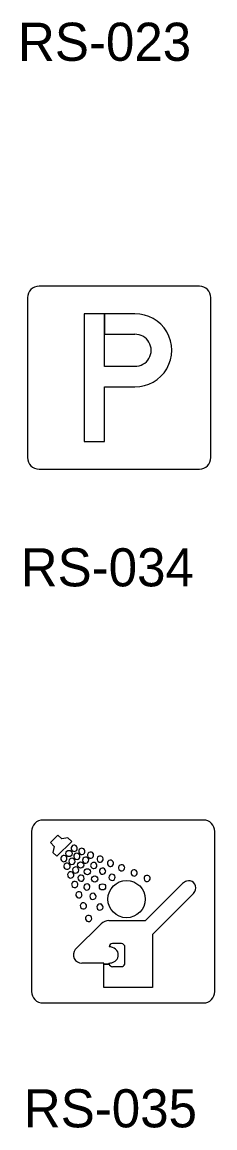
# Model space of a CAD drawing. Extents: x 42133 to 45533, y 41351 to 47951.
# Drawn here: x 42901.3 to 42939.1, y 41989.2 to 42206.7 of the extents above; entities that cross this region are included whole.
import ezdxf

# ---------------------------------------------------------------- set-up
doc = ezdxf.new("R2010")
doc.units = 0
doc.layers.add('P_TRAF_SIGN_SignDetails', color=7, linetype='Continuous')

msp = doc.modelspace()

# ---------------------------------------------------------------- linework, layer by layer
at = {"layer": 'P_TRAF_SIGN_SignDetails'}
for p, q in [((42936.11, 42154.77), (42904.63, 42154.77)), ((42902.38, 42152.52), (42902.38, 42121.03)), ((42938.36, 42121.03), (42938.36, 42152.52)), ((42904.63, 42118.78), (42936.11, 42118.78)), ((42936.89, 42049.76), (42905.42, 42049.76)), ((42903.17, 42047.51), (42903.17, 42016.03)), ((42939.15, 42016.03), (42939.15, 42047.51)), ((42905.42, 42013.78), (42936.89, 42013.78))]:
    msp.add_line(p, q, dxfattribs=at)
for points in [[(42917.5, 42149.32), (42913.48, 42149.32), (42913.48, 42124.21), (42917.5, 42124.21), (42917.5, 42134.98), (42923.43, 42134.98)], [(42923.43, 42149.32), (42917.5, 42149.32), (42917.5, 42145.31), (42923.43, 42145.31)], [(42923.43, 42138.99), (42917.5, 42138.99), (42917.5, 42149.32)], [(42918.34, 42029.97), (42925.55, 42029.97), (42932.82, 42037.26)], [(42918.34, 42029.97), (42925.55, 42029.97), (42932.82, 42037.26)], [(42918.34, 42029.97), (42925.55, 42029.97), (42932.82, 42037.26)], [(42934.86, 42035.23), (42926.89, 42027.23), (42926.89, 42016.79), (42917.34, 42016.79), (42917.34, 42021.62), (42913.02, 42021.62)], [(42934.86, 42035.23), (42926.89, 42027.23), (42926.89, 42016.79), (42917.34, 42016.79), (42917.34, 42021.43), (42918.39, 42021.43)], [(42934.86, 42035.23), (42926.89, 42027.23), (42926.89, 42016.79), (42917.34, 42016.79), (42917.34, 42021.43), (42918.39, 42021.43)], [(42911.74, 42024.27), (42916.83, 42029.37)], [(42911.74, 42024.27), (42916.83, 42029.37)], [(42911.74, 42024.27), (42916.83, 42029.37)], [(42920.77, 42025.45), (42919.08, 42025.45)], [(42920.77, 42025.45), (42919.08, 42025.45)], [(42920.77, 42025.45), (42919.08, 42025.45)], [(42921.49, 42021.62), (42921.49, 42024.74)], [(42921.49, 42021.62), (42921.49, 42024.74)], [(42921.49, 42021.62), (42921.49, 42024.74)], [(42918.39, 42021.43), (42917.34, 42021.43), (42917.34, 42021.62), (42913.02, 42021.62)], [(42918.39, 42021.43), (42917.34, 42021.43), (42917.34, 42021.62), (42913.02, 42021.62)], [(42919.08, 42020.92), (42919.08, 42020.92), (42920.77, 42020.92), (42920.77, 42020.92)], [(42919.08, 42020.92), (42919.08, 42020.92), (42920.77, 42020.92), (42920.77, 42020.92)], [(42919.08, 42020.92), (42919.08, 42020.92), (42920.77, 42020.92), (42920.77, 42020.92)]]:
    msp.add_lwpolyline(points, dxfattribs=at)
msp.add_lwpolyline([(42907.37, 42043.35), (42908.11, 42042.62), (42911.05, 42045.56), (42910.31, 42046.29), (42909.08, 42046.06), (42908.35, 42046.79), (42906.87, 42045.32), (42907.61, 42044.58)], close=True, dxfattribs=at)
msp.add_lwpolyline([(42907.37, 42043.35), (42908.11, 42042.62), (42911.05, 42045.56), (42910.31, 42046.29), (42909.08, 42046.06), (42908.35, 42046.79), (42906.87, 42045.32), (42907.61, 42044.58)], close=True, dxfattribs=at)
msp.add_lwpolyline([(42907.37, 42043.35), (42908.11, 42042.62), (42911.05, 42045.56), (42910.31, 42046.29), (42909.08, 42046.06), (42908.35, 42046.79), (42906.87, 42045.32), (42907.61, 42044.58)], close=True, dxfattribs=at)
for centre, radius in [((42910.51, 42043.18), 0.611), ((42910.51, 42043.18), 0.611), ((42910.51, 42043.18), 0.611), ((42912.8, 42040.91), 0.605), ((42912.8, 42040.91), 0.605), ((42912.8, 42040.91), 0.605), ((42914.12, 42039.58), 0.605), ((42914.12, 42039.58), 0.605), ((42914.12, 42039.58), 0.605), ((42915.56, 42038.15), 0.605), ((42915.56, 42038.15), 0.605), ((42915.56, 42038.15), 0.605), ((42917.09, 42036.62), 0.605), ((42917.09, 42036.62), 0.605), ((42917.09, 42036.62), 0.605), ((42921.81, 42034.2), 3.66), ((42921.81, 42034.2), 3.66), ((42921.81, 42034.2), 3.66)]:
    msp.add_circle(centre, radius, dxfattribs=at)
for centre, radius, start, end in [((42904.63, 42152.51), 2.25, 90, 180), ((42936.11, 42152.51), 2.25, 360, 90), ((42923.52, 42142.15), 7.17, 269.2807, 90.7193), ((42923.5, 42142.15), 3.15, 268.7196, 91.2804), ((42904.63, 42121.04), 2.25, 180, 270), ((42936.11, 42121.04), 2.25, 270, 0), ((42905.42, 42047.51), 2.25, 90, 180), ((42936.9, 42047.51), 2.25, 360, 90), ((42911.53, 42044.2), 0.614, 98.3789, 188.1597), ((42911.53, 42044.2), 0.614, 98.3789, 188.1597), ((42911.53, 42044.2), 0.614, 98.3789, 188.1597), ((42911.53, 42044.21), 0.61, 8.0336, 98.2816), ((42911.53, 42044.21), 0.61, 8.0336, 98.2816), ((42911.53, 42044.21), 0.61, 8.0336, 98.2816), ((42909.5, 42042.17), 0.611, 81.7795, 171.9093), ((42909.5, 42042.17), 0.611, 81.7795, 171.9093), ((42909.5, 42042.17), 0.611, 81.7795, 171.9093), ((42909.5, 42042.17), 0.612, 351.7168, 81.6536), ((42909.5, 42042.17), 0.612, 351.7168, 81.6536), ((42909.5, 42042.17), 0.612, 351.7168, 81.6536), ((42911.53, 42044.2), 0.611, 188.2859, 278.3788), ((42911.53, 42044.2), 0.611, 188.2859, 278.3788), ((42911.53, 42044.2), 0.611, 188.2859, 278.3788), ((42912.06, 42042.61), 0.606, 92.7577, 182.6456), ((42912.06, 42042.61), 0.606, 92.7577, 182.6456), ((42912.06, 42042.61), 0.606, 92.7577, 182.6456), ((42912.06, 42042.61), 0.603, 182.5563, 272.9843), ((42912.06, 42042.61), 0.603, 182.5563, 272.9843), ((42912.06, 42042.61), 0.603, 182.5563, 272.9843), ((42911.53, 42044.2), 0.611, 278.3153, 8.2319), ((42911.53, 42044.2), 0.611, 278.3153, 8.2319), ((42911.53, 42044.2), 0.611, 278.3153, 8.2319), ((42912.06, 42042.61), 0.607, 2.9827, 92.63), ((42912.06, 42042.61), 0.607, 2.9827, 92.63), ((42912.06, 42042.61), 0.607, 2.9827, 92.63), ((42912.06, 42042.62), 0.605, 272.6978, 2.7441), ((42912.06, 42042.62), 0.605, 272.6978, 2.7441), ((42912.06, 42042.62), 0.605, 272.6978, 2.7441), ((42913.03, 42043.59), 0.612, 98.2969, 188.2579), ((42913.03, 42043.59), 0.612, 98.2969, 188.2579), ((42913.03, 42043.59), 0.612, 98.2969, 188.2579), ((42913.03, 42043.59), 0.609, 188.2026, 278.4745), ((42913.03, 42043.59), 0.609, 188.2026, 278.4745), ((42913.03, 42043.59), 0.609, 188.2026, 278.4745), ((42913.03, 42043.59), 0.611, 8.1756, 98.3437), ((42913.03, 42043.59), 0.611, 8.1756, 98.3437), ((42913.03, 42043.59), 0.611, 8.1756, 98.3437), ((42913.04, 42043.59), 0.61, 278.1, 8.2388), ((42913.04, 42043.59), 0.61, 278.1, 8.2388), ((42913.04, 42043.59), 0.61, 278.1, 8.2388), ((42913.77, 42041.88), 0.604, 93.884, 184.3141), ((42913.77, 42041.88), 0.604, 93.884, 184.3141), ((42913.77, 42041.88), 0.604, 93.884, 184.3141), ((42913.78, 42041.88), 0.603, 3.8929, 94.4102), ((42913.78, 42041.88), 0.603, 3.8929, 94.4102), ((42913.78, 42041.88), 0.603, 3.8929, 94.4102), ((42914.75, 42042.85), 0.613, 98.3393, 188.1643), ((42914.75, 42042.85), 0.613, 98.3393, 188.1643), ((42914.75, 42042.85), 0.613, 98.3393, 188.1643), ((42914.75, 42042.86), 0.612, 188.4062, 278.2076), ((42914.75, 42042.86), 0.612, 188.4062, 278.2076), ((42914.75, 42042.86), 0.612, 188.4062, 278.2076), ((42914.75, 42042.86), 0.612, 8.3424, 98.1774), ((42914.75, 42042.86), 0.612, 8.3424, 98.1774), ((42914.75, 42042.86), 0.612, 8.3424, 98.1774), ((42914.75, 42042.86), 0.611, 278.2485, 8.381), ((42914.75, 42042.86), 0.611, 278.2485, 8.381), ((42914.75, 42042.86), 0.611, 278.2485, 8.381), ((42916.62, 42042.07), 0.613, 98.3449, 188.1744), ((42916.62, 42042.07), 0.613, 98.3449, 188.1744), ((42916.62, 42042.07), 0.613, 98.3449, 188.1744), ((42916.62, 42042.07), 0.613, 8.3603, 98.0768), ((42916.62, 42042.07), 0.613, 8.3603, 98.0768), ((42916.62, 42042.07), 0.613, 8.3603, 98.0768), ((42909.5, 42042.17), 0.612, 171.7201, 261.6504), ((42909.5, 42042.17), 0.612, 171.7201, 261.6504), ((42909.5, 42042.17), 0.612, 171.7201, 261.6504), ((42909.5, 42042.17), 0.612, 261.9115, 351.7773), ((42909.5, 42042.17), 0.612, 261.9115, 351.7773), ((42909.5, 42042.17), 0.612, 261.9115, 351.7773), ((42910.12, 42040.67), 0.611, 81.7191, 171.9343), ((42910.12, 42040.67), 0.611, 81.7191, 171.9343), ((42910.12, 42040.67), 0.611, 81.7191, 171.9343), ((42910.12, 42040.67), 0.612, 171.9294, 261.779), ((42910.12, 42040.67), 0.612, 171.9294, 261.779), ((42910.12, 42040.67), 0.612, 171.9294, 261.779), ((42910.12, 42040.67), 0.611, 261.7105, 351.758), ((42910.12, 42040.67), 0.611, 261.7105, 351.758), ((42910.12, 42040.67), 0.611, 261.7105, 351.758), ((42910.12, 42040.67), 0.613, 351.859, 81.6374), ((42910.12, 42040.67), 0.613, 351.859, 81.6374), ((42910.12, 42040.67), 0.613, 351.859, 81.6374), ((42911.09, 42041.64), 0.606, 87.2417, 177.1589), ((42911.09, 42041.64), 0.606, 87.2417, 177.1589), ((42911.09, 42041.64), 0.606, 87.2417, 177.1589), ((42911.09, 42041.64), 0.606, 177.174, 267.1788), ((42911.09, 42041.64), 0.606, 177.174, 267.1788), ((42911.09, 42041.64), 0.606, 177.174, 267.1788), ((42911.09, 42041.64), 0.606, 267.2609, 87.2012), ((42911.09, 42041.64), 0.606, 267.2609, 87.2012), ((42911.09, 42041.64), 0.606, 267.2609, 87.2012), ((42911.82, 42039.93), 0.606, 85.8519, 175.9499), ((42911.82, 42039.93), 0.606, 85.8519, 175.9499), ((42911.82, 42039.93), 0.606, 85.8519, 175.9499), ((42911.82, 42039.93), 0.606, 355.8366, 85.9653), ((42911.82, 42039.93), 0.606, 355.8366, 85.9653), ((42911.82, 42039.93), 0.606, 355.8366, 85.9653), ((42913.77, 42041.88), 0.604, 184.0395, 274.3235), ((42913.77, 42041.88), 0.604, 184.0395, 274.3235), ((42913.77, 42041.88), 0.604, 184.0395, 274.3235), ((42913.78, 42041.88), 0.605, 273.9416, 4.2047), ((42913.78, 42041.88), 0.605, 273.9416, 4.2047), ((42913.78, 42041.88), 0.605, 273.9416, 4.2047), ((42915.37, 42040.83), 0.606, 94.0532, 274.152), ((42915.37, 42040.83), 0.606, 94.0532, 274.152), ((42915.37, 42040.83), 0.606, 94.0532, 274.152), ((42915.37, 42040.83), 0.606, 4.1132, 94.2566), ((42915.37, 42040.83), 0.606, 4.1132, 94.2566), ((42915.37, 42040.83), 0.606, 4.1132, 94.2566), ((42915.37, 42040.83), 0.607, 274.1331, 4.0182), ((42915.37, 42040.83), 0.607, 274.1331, 4.0182), ((42915.37, 42040.83), 0.607, 274.1331, 4.0182), ((42916.62, 42042.08), 0.612, 188.2324, 278.13), ((42916.62, 42042.08), 0.612, 188.2324, 278.13), ((42916.62, 42042.08), 0.612, 188.2324, 278.13), ((42917.1, 42039.7), 0.608, 94.2402, 184.0486), ((42917.1, 42039.7), 0.608, 94.2402, 184.0486), ((42917.1, 42039.7), 0.608, 94.2402, 184.0486), ((42916.62, 42042.08), 0.613, 278.3364, 8.2142), ((42916.62, 42042.08), 0.613, 278.3364, 8.2142), ((42916.62, 42042.08), 0.613, 278.3364, 8.2142), ((42917.1, 42039.7), 0.606, 4.163, 94.155), ((42917.1, 42039.7), 0.606, 4.163, 94.155), ((42917.1, 42039.7), 0.606, 4.163, 94.155), ((42918.65, 42041.25), 0.61, 98.2215, 188.408), ((42918.65, 42041.25), 0.61, 98.2215, 188.408), ((42918.65, 42041.25), 0.61, 98.2215, 188.408), ((42918.65, 42041.24), 0.609, 188.2429, 278.4147), ((42918.65, 42041.24), 0.609, 188.2429, 278.4147), ((42918.65, 42041.24), 0.609, 188.2429, 278.4147), ((42918.65, 42041.25), 0.61, 8.0113, 98.2999), ((42918.65, 42041.25), 0.61, 8.0113, 98.2999), ((42918.65, 42041.25), 0.61, 8.0113, 98.2999), ((42918.65, 42041.24), 0.607, 277.9783, 8.3923), ((42918.65, 42041.24), 0.607, 277.9783, 8.3923), ((42918.65, 42041.24), 0.607, 277.9783, 8.3923), ((42920.84, 42040.37), 0.611, 98.303, 188.3265), ((42920.84, 42040.37), 0.611, 98.303, 188.3265), ((42920.84, 42040.37), 0.611, 98.303, 188.3265), ((42920.84, 42040.36), 0.613, 8.4005, 98.0718), ((42920.84, 42040.36), 0.613, 8.4005, 98.0718), ((42920.84, 42040.36), 0.613, 8.4005, 98.0718), ((42920.84, 42040.37), 0.613, 278.3772, 8.1893), ((42920.84, 42040.37), 0.613, 278.3772, 8.1893), ((42920.84, 42040.37), 0.613, 278.3772, 8.1893), ((42910.85, 42038.96), 0.613, 81.8385, 171.6579), ((42910.85, 42038.96), 0.613, 81.8385, 171.6579), ((42910.85, 42038.96), 0.613, 81.8385, 171.6579), ((42910.85, 42038.96), 0.613, 171.8845, 261.6236), ((42910.85, 42038.96), 0.613, 171.8845, 261.6236), ((42910.85, 42038.96), 0.613, 171.8845, 261.6236), ((42910.85, 42038.96), 0.613, 261.9442, 351.7289), ((42910.85, 42038.96), 0.613, 261.9442, 351.7289), ((42910.85, 42038.96), 0.613, 261.9442, 351.7289), ((42910.85, 42038.96), 0.611, 351.7206, 81.7478), ((42910.85, 42038.96), 0.611, 351.7206, 81.7478), ((42910.85, 42038.96), 0.611, 351.7206, 81.7478), ((42911.82, 42039.93), 0.607, 176.0031, 265.8896), ((42911.82, 42039.93), 0.607, 176.0031, 265.8896), ((42911.82, 42039.93), 0.607, 176.0031, 265.8896), ((42911.82, 42039.93), 0.605, 265.7806, 355.9164), ((42911.82, 42039.93), 0.605, 265.7806, 355.9164), ((42911.82, 42039.93), 0.605, 265.7806, 355.9164), ((42912.88, 42038.33), 0.605, 85.7154, 176.0265), ((42912.88, 42038.33), 0.605, 85.7154, 176.0265), ((42912.88, 42038.33), 0.605, 85.7154, 176.0265), ((42912.88, 42038.33), 0.606, 175.8246, 265.8444), ((42912.88, 42038.33), 0.606, 175.8246, 265.8444), ((42912.88, 42038.33), 0.606, 175.8246, 265.8444), ((42912.88, 42038.33), 0.607, 265.8238, 355.9791), ((42912.88, 42038.33), 0.607, 265.8238, 355.9791), ((42912.88, 42038.33), 0.607, 265.8238, 355.9791), ((42912.88, 42038.33), 0.605, 355.8566, 86.075), ((42912.88, 42038.33), 0.605, 355.8566, 86.075), ((42912.88, 42038.33), 0.605, 355.8566, 86.075), ((42917.1, 42039.7), 0.604, 184.0703, 274.3507), ((42917.1, 42039.7), 0.604, 184.0703, 274.3507), ((42917.1, 42039.7), 0.604, 184.0703, 274.3507), ((42917.11, 42039.7), 0.603, 273.7767, 4.4494), ((42917.11, 42039.7), 0.603, 273.7767, 4.4494), ((42917.11, 42039.7), 0.603, 273.7767, 4.4494), ((42918.96, 42038.49), 0.608, 94.1682, 184.0887), ((42918.96, 42038.49), 0.608, 94.1682, 184.0887), ((42918.96, 42038.49), 0.608, 94.1682, 184.0887), ((42918.96, 42038.49), 0.608, 184.3273, 274.0664), ((42918.96, 42038.49), 0.608, 184.3273, 274.0664), ((42918.96, 42038.49), 0.608, 184.3273, 274.0664), ((42918.96, 42038.49), 0.608, 4.3272, 94.0794), ((42918.96, 42038.49), 0.608, 4.3272, 94.0794), ((42918.96, 42038.49), 0.608, 4.3272, 94.0794), ((42918.96, 42038.49), 0.608, 274.2027, 4.0392), ((42918.96, 42038.49), 0.608, 274.2027, 4.0392), ((42918.96, 42038.49), 0.608, 274.2027, 4.0392), ((42920.84, 42040.36), 0.612, 188.2531, 278.1722), ((42920.84, 42040.36), 0.612, 188.2531, 278.1722), ((42920.84, 42040.36), 0.612, 188.2531, 278.1722), ((42923.3, 42039.35), 0.614, 98.4037, 188.0527), ((42923.3, 42039.35), 0.614, 98.4037, 188.0527), ((42923.3, 42039.35), 0.614, 98.4037, 188.0527), ((42923.3, 42039.35), 0.612, 188.2534, 278.2189), ((42923.3, 42039.35), 0.612, 188.2534, 278.2189), ((42923.3, 42039.35), 0.612, 188.2534, 278.2189), ((42923.3, 42039.35), 0.613, 8.4063, 98.015), ((42923.3, 42039.35), 0.613, 8.4063, 98.015), ((42923.3, 42039.35), 0.613, 8.4063, 98.015), ((42923.3, 42039.35), 0.611, 278.1971, 8.2948), ((42923.3, 42039.35), 0.611, 278.1971, 8.2948), ((42923.3, 42039.35), 0.611, 278.1971, 8.2948), ((42925.84, 42038.28), 0.608, 98.0697, 188.3008), ((42925.84, 42038.28), 0.608, 98.0697, 188.3008), ((42925.84, 42038.28), 0.608, 98.0697, 188.3008), ((42925.84, 42038.27), 0.608, 187.8451, 278.3836), ((42925.84, 42038.27), 0.608, 187.8451, 278.3836), ((42925.84, 42038.27), 0.608, 187.8451, 278.3836), ((42925.84, 42038.28), 0.609, 8.1083, 98.439), ((42925.84, 42038.28), 0.609, 8.1083, 98.439), ((42925.84, 42038.28), 0.609, 8.1083, 98.439), ((42925.84, 42038.28), 0.61, 278.0769, 8.3602), ((42925.84, 42038.28), 0.61, 278.0769, 8.3602), ((42925.84, 42038.28), 0.61, 278.0769, 8.3602), ((42911.63, 42037.08), 0.61, 171.6237, 261.7938), ((42911.63, 42037.08), 0.61, 171.6237, 261.7938), ((42911.63, 42037.08), 0.61, 171.6237, 261.7938), ((42911.63, 42037.09), 0.609, 81.5216, 171.9311), ((42911.63, 42037.09), 0.609, 81.5216, 171.9311), ((42911.63, 42037.09), 0.609, 81.5216, 171.9311), ((42911.63, 42037.08), 0.611, 261.7211, 351.7946), ((42911.63, 42037.08), 0.611, 261.7211, 351.7946), ((42911.63, 42037.08), 0.611, 261.7211, 351.7946), ((42911.63, 42037.09), 0.61, 351.645, 81.8195), ((42911.63, 42037.09), 0.61, 351.645, 81.8195), ((42911.63, 42037.09), 0.61, 351.645, 81.8195), ((42914.01, 42036.6), 0.607, 85.8697, 175.7366), ((42914.01, 42036.6), 0.607, 85.8697, 175.7366), ((42914.01, 42036.6), 0.607, 85.8697, 175.7366), ((42914.01, 42036.6), 0.607, 175.8768, 265.8343), ((42914.01, 42036.6), 0.607, 175.8768, 265.8343), ((42914.01, 42036.6), 0.607, 175.8768, 265.8343), ((42914.01, 42036.6), 0.607, 265.8575, 355.7338), ((42914.01, 42036.6), 0.607, 265.8575, 355.7338), ((42914.01, 42036.6), 0.607, 265.8575, 355.7338), ((42914.01, 42036.6), 0.607, 355.8224, 85.8758), ((42914.01, 42036.6), 0.607, 355.8224, 85.8758), ((42914.01, 42036.6), 0.607, 355.8224, 85.8758), ((42934.4, 42035.7), 2.21, 123.0408, 135.4803), ((42934.4, 42035.7), 2.21, 123.0408, 135.4803), ((42934.4, 42035.7), 2.21, 123.0408, 135.4803), ((42934.13, 42036.11), 1.73, 108.9254, 122.8888), ((42934.13, 42036.11), 1.73, 108.9254, 122.8888), ((42934.13, 42036.11), 1.73, 108.9254, 122.8888), ((42934.03, 42036.43), 1.39, 344.1209, 109.261), ((42934.03, 42036.43), 1.39, 344.1209, 109.261), ((42934.03, 42036.43), 1.39, 344.1209, 109.261), ((42933.78, 42036.5), 1.64, 330.0702, 344.4095), ((42933.78, 42036.5), 1.64, 330.0702, 344.4095), ((42933.78, 42036.5), 1.64, 330.0702, 344.4095), ((42912.46, 42035.05), 0.613, 81.9631, 171.5999), ((42912.46, 42035.05), 0.613, 81.9631, 171.5999), ((42912.46, 42035.05), 0.613, 81.9631, 171.5999), ((42912.46, 42035.06), 0.613, 171.856, 261.6404), ((42912.46, 42035.06), 0.613, 171.856, 261.6404), ((42912.46, 42035.06), 0.613, 171.856, 261.6404), ((42912.46, 42035.06), 0.613, 261.9374, 351.7474), ((42912.46, 42035.06), 0.613, 261.9374, 351.7474), ((42912.46, 42035.06), 0.613, 261.9374, 351.7474), ((42912.46, 42035.06), 0.61, 351.6796, 81.8833), ((42912.46, 42035.06), 0.61, 351.6796, 81.8833), ((42912.46, 42035.06), 0.61, 351.6796, 81.8833), ((42915.22, 42034.74), 0.607, 85.9795, 175.9061), ((42915.22, 42034.74), 0.607, 85.9795, 175.9061), ((42915.22, 42034.74), 0.607, 85.9795, 175.9061), ((42915.22, 42034.74), 0.607, 175.8687, 265.7696), ((42915.22, 42034.74), 0.607, 175.8687, 265.7696), ((42915.22, 42034.74), 0.607, 175.8687, 265.7696), ((42915.21, 42034.74), 0.61, 266.0795, 355.6187), ((42915.21, 42034.74), 0.61, 266.0795, 355.6187), ((42915.21, 42034.74), 0.61, 266.0795, 355.6187), ((42915.21, 42034.74), 0.609, 355.9475, 85.8165), ((42915.21, 42034.74), 0.609, 355.9475, 85.8165), ((42915.21, 42034.74), 0.609, 355.9475, 85.8165), ((42933.17, 42036.92), 2.39, 315.0468, 317.4898), ((42933.17, 42036.92), 2.39, 315.0468, 317.4898), ((42933.17, 42036.92), 2.39, 315.0468, 317.4898), ((42933.42, 42036.7), 2.06, 317.1158, 330.1178), ((42933.42, 42036.7), 2.06, 317.1158, 330.1178), ((42933.42, 42036.7), 2.06, 317.1158, 330.1178), ((42913.34, 42032.87), 0.613, 81.8599, 171.7189), ((42913.34, 42032.87), 0.613, 81.8599, 171.7189), ((42913.34, 42032.87), 0.613, 81.8599, 171.7189), ((42913.34, 42032.87), 0.613, 171.845, 261.6003), ((42913.34, 42032.87), 0.613, 171.845, 261.6003), ((42913.34, 42032.87), 0.613, 171.845, 261.6003), ((42913.34, 42032.87), 0.613, 261.9333, 351.6297), ((42913.34, 42032.87), 0.613, 261.9333, 351.6297), ((42913.34, 42032.87), 0.613, 261.9333, 351.6297), ((42913.34, 42032.87), 0.61, 351.5329, 81.8024), ((42913.34, 42032.87), 0.61, 351.5329, 81.8024), ((42913.34, 42032.87), 0.61, 351.5329, 81.8024), ((42916.59, 42032.64), 0.606, 175.7783, 265.8668), ((42916.59, 42032.64), 0.606, 175.7783, 265.8668), ((42916.59, 42032.64), 0.606, 175.7783, 265.8668), ((42916.59, 42032.64), 0.606, 85.8047, 175.8643), ((42916.59, 42032.64), 0.606, 85.8047, 175.8643), ((42916.59, 42032.64), 0.606, 85.8047, 175.8643), ((42916.59, 42032.64), 0.606, 265.8308, 355.964), ((42916.59, 42032.64), 0.606, 265.8308, 355.964), ((42916.59, 42032.64), 0.606, 265.8308, 355.964), ((42916.59, 42032.64), 0.605, 355.8786, 85.9542), ((42916.59, 42032.64), 0.605, 355.8786, 85.9542), ((42916.59, 42032.64), 0.605, 355.8786, 85.9542), ((42914.36, 42030.41), 0.612, 171.8843, 261.6944), ((42914.36, 42030.41), 0.612, 171.8843, 261.6944), ((42914.36, 42030.41), 0.612, 171.8843, 261.6944), ((42914.35, 42030.41), 0.609, 81.5668, 171.9489), ((42914.35, 42030.41), 0.609, 81.5668, 171.9489), ((42914.35, 42030.41), 0.609, 81.5668, 171.9489), ((42914.36, 42030.4), 0.61, 261.6559, 351.8243), ((42914.36, 42030.4), 0.61, 261.6559, 351.8243), ((42914.36, 42030.4), 0.61, 261.6559, 351.8243), ((42914.36, 42030.41), 0.61, 351.6272, 81.9005), ((42914.36, 42030.41), 0.61, 351.6272, 81.9005), ((42914.36, 42030.41), 0.61, 351.6272, 81.9005), ((42918.33, 42027.79), 2.18, 89.9536, 133.5967), ((42918.33, 42027.79), 2.18, 89.9536, 133.5967), ((42918.33, 42027.79), 2.18, 89.9536, 133.5967), ((42919.08, 42024.73), 0.717, 90.1494, 174.1826), ((42919.08, 42024.73), 0.717, 90.1494, 174.1826), ((42919.08, 42024.73), 0.717, 90.1494, 174.1826), ((42920.77, 42024.71), 0.737, 84.2918, 90.0162), ((42920.77, 42024.71), 0.737, 84.2918, 90.0162), ((42920.77, 42024.71), 0.737, 84.2918, 90.0162), ((42920.78, 42024.74), 0.713, 0.5554, 84.6765), ((42920.78, 42024.74), 0.713, 0.5554, 84.6765), ((42920.78, 42024.74), 0.713, 0.5554, 84.6765), ((42913.02, 42023.25), 1.63, 141.4526, 270.0171), ((42913.02, 42023.25), 1.63, 141.4526, 270.0171), ((42913.02, 42023.25), 1.63, 141.4526, 270.0171), ((42918.39, 42022.48), 2.33, 73.9253, 90.5166), ((42918.39, 42022.48), 2.33, 73.9253, 90.5166), ((42918.39, 42022.48), 2.33, 73.9253, 90.5166), ((42918.62, 42023.2), 1.57, 22.6713, 74.9402), ((42918.62, 42023.2), 1.57, 22.6713, 74.9402), ((42918.62, 42023.2), 1.57, 22.6713, 74.9402), ((42918.65, 42023.23), 1.54, 296.0003, 22.1092), ((42918.65, 42023.23), 1.54, 296.0003, 22.1092), ((42918.65, 42023.23), 1.54, 296.0003, 22.1092), ((42918.37, 42024.09), 2.46, 269.8638, 278.6367), ((42918.37, 42024.09), 2.46, 269.8638, 278.6367), ((42918.37, 42024.09), 2.46, 269.8638, 278.6367), ((42919.08, 42021.63), 0.715, 179.9289, 269.9166), ((42919.08, 42021.63), 0.715, 179.9289, 196.3004), ((42919.08, 42021.63), 0.715, 179.9289, 196.3004), ((42919.08, 42021.63), 0.715, 196.3129, 269.9166), ((42919.08, 42021.63), 0.715, 196.3129, 269.9166), ((42918.46, 42023.58), 1.94, 278.2545, 296.3392), ((42918.46, 42023.58), 1.94, 278.2545, 296.3392), ((42918.46, 42023.58), 1.94, 278.2545, 296.3392), ((42920.77, 42021.64), 0.72, 269.6904, 340.4824), ((42920.77, 42021.64), 0.72, 269.6904, 340.4824), ((42920.77, 42021.64), 0.72, 269.6904, 340.4824), ((42920.8, 42021.62), 0.693, 340.9431, 0.0698), ((42920.8, 42021.62), 0.693, 340.9431, 0.0698), ((42920.8, 42021.62), 0.693, 340.9431, 0.0698), ((42905.42, 42016.03), 2.25, 180, 270), ((42936.9, 42016.03), 2.25, 270, 0)]:
    msp.add_arc(centre, radius, start, end, dxfattribs=at)

# ---------------------------------------------------------------- texts
for s, p in [('RS-023', (42900.49, 42199.09)), ('RS-034', (42901.03, 42095.72)), ('RS-035', (42901.64, 41989.31))]:
    msp.add_text(s, height=7.5, dxfattribs=at).set_placement(p)

doc.saveas('drawing.dxf')
